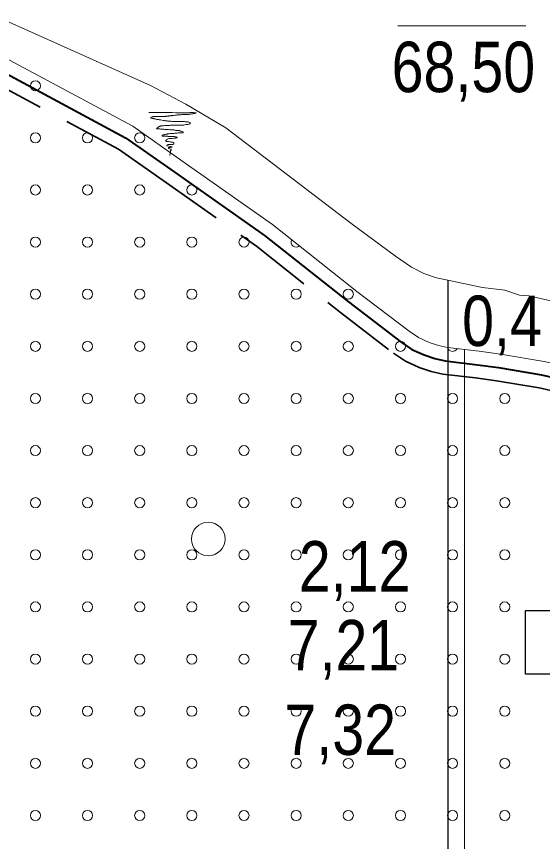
# Model space of a CAD drawing. Extents: x 640104 to 640970, y 6442278 to 6442689.
# Drawn here: x 640245.12 to 640276.39, y 6442589.62 to 6442638.69 of the extents above; entities that cross this region are included whole.
import ezdxf
from ezdxf.enums import TextEntityAlignment as Align

# ---------------------------------------------------------------- set-up
doc = ezdxf.new("R2010")
doc.units = 0
doc.header["$LTSCALE"] = 1.2
doc.linetypes.add('MEDIUM_DASHED', pattern=[4.5, 3, -1.5])
for name, color, linetype, lineweight in [('31', 7, 'Continuous', 13), ('32', 7, 'Continuous', 25), ('33', 7, 'Continuous', 13), ('35', 7, 'Continuous', 35), ('40', 7, 'Continuous', 13), ('43', 7, 'Continuous', 13), ('47', 7, 'Continuous', 13)]:
    doc.layers.add(name, color=color, linetype=linetype, lineweight=lineweight)

msp = doc.modelspace()

# ---------------------------------------------------------------- linework, layer by layer
at = {"layer": '31'}
for points in [[(640243.91, 6442638.69), (640253.09, 6442634.58), (640255.2, 6442633.48), (640257.56, 6442632.06), (640261.58, 6442629.01), (640265, 6442626.4), (640267.65, 6442624.44), (640268.61, 6442623.79), (640269.33, 6442623.41), (640270.09, 6442623.14), (640270.76, 6442623), (640271.59, 6442622.83), (640272.83, 6442622.58), (640274.15, 6442622.41), (640275.03, 6442622.12), (640275.59, 6442622.07), (640277.84, 6442621.56), (640282.07, 6442620.29), (640283.81, 6442619.85), (640292.79, 6442617.95), (640300.96, 6442616.04)], [(640244.14, 6442636.4), (640252.04, 6442632.16), (640254.96, 6442630.1), (640260.34, 6442626.31), (640265.36, 6442622.34), (640268.47, 6442619.97), (640269.03, 6442619.59), (640269.65, 6442619.31), (640270.21, 6442619.12), (640270.74, 6442619), (640272.62, 6442618.78), (640273.9, 6442618.6), (640276.5, 6442618.17), (640279.42, 6442617.51), (640285.18, 6442616.2), (640293.34, 6442614.31), (640302.22, 6442612.41), (640310.19, 6442611.24), (640319.16, 6442609.71), (640327.89, 6442607.76), (640337.5, 6442606.29), (640350.61, 6442605.07), (640361.71, 6442604.69)]]:
    msp.add_lwpolyline(points, dxfattribs=at)
at = {"layer": '32', "lineweight": 13}
msp.add_line((640267.79, 6442638.14), (640275.4, 6442638.14), dxfattribs=at)
at = {"layer": '32'}
msp.add_line((640270.76, 6442623), (640270.76, 6442501), dxfattribs=at)
at = {"layer": '33'}
msp.add_lwpolyline([(640271.76, 6442583), (640271.76, 6442618.88), (640270.76, 6442619), (640270.76, 6442583)], close=True, dxfattribs=at)
at = {"layer": '33', "lineweight": 25}
msp.add_lwpolyline([(640275.38, 6442603.37), (640284.09, 6442603.37), (640284.09, 6442599.57), (640275.38, 6442599.57)], close=True, dxfattribs=at)
at = {"layer": '35', "lineweight": 40}
msp.add_lwpolyline([(640243.75, 6442635.7), (640251.61, 6442631.47), (640254.5, 6442629.45), (640259.86, 6442625.67), (640264.87, 6442621.71), (640268, 6442619.32), (640268.63, 6442618.89), (640269.35, 6442618.56), (640270, 6442618.35), (640270.6, 6442618.21), (640272.52, 6442617.98), (640273.78, 6442617.81), (640276.34, 6442617.38), (640279.24, 6442616.73), (640285.01, 6442615.42), (640293.17, 6442613.53), (640302.08, 6442611.63), (640310.07, 6442610.45), (640319, 6442608.92), (640327.74, 6442606.97), (640337.4, 6442605.49), (640350.56, 6442604.27), (640361.69, 6442603.89)], dxfattribs=at)
at = {"layer": '35', "linetype": 'MEDIUM_DASHED'}
msp.add_lwpolyline([(640243.37, 6442635), (640251.19, 6442630.79), (640254.04, 6442628.79), (640259.39, 6442625.03), (640264.38, 6442621.08), (640267.53, 6442618.67), (640268.24, 6442618.19), (640269.06, 6442617.81), (640269.78, 6442617.57), (640270.47, 6442617.42), (640272.42, 6442617.19), (640273.66, 6442617.02), (640276.19, 6442616.6), (640279.06, 6442615.94), (640284.83, 6442614.64), (640292.99, 6442612.74), (640301.93, 6442610.84), (640309.94, 6442609.66), (640318.85, 6442608.14), (640327.59, 6442606.19), (640337.3, 6442604.7), (640350.51, 6442603.47), (640361.68, 6442603.09)], dxfattribs=at)
at = {"layer": '40'}
for points in [[(640252.99, 6442632.98), (640253.03, 6442632.98), (640253.1, 6442632.98), (640253.17, 6442632.98), (640253.19, 6442632.98), (640253.26, 6442632.98), (640253.36, 6442632.98), (640253.58, 6442632.98), (640253.7, 6442632.98), (640253.72, 6442632.98), (640253.75, 6442632.98), (640253.8, 6442632.98), (640253.85, 6442632.98), (640253.92, 6442632.98), (640253.98, 6442632.98), (640254.02, 6442632.98), (640254.08, 6442632.98), (640254.12, 6442632.98), (640254.17, 6442632.98), (640254.23, 6442632.98), (640254.26, 6442632.98), (640254.31, 6442632.98), (640254.37, 6442632.98), (640254.6, 6442632.97), (640254.8, 6442632.96), (640254.87, 6442632.96), (640254.91, 6442632.96), (640254.93, 6442632.96), (640254.96, 6442632.96), (640255.01, 6442632.96), (640255.08, 6442632.97), (640255.11, 6442632.97), (640255.13, 6442632.97), (640255.15, 6442632.97), (640255.17, 6442632.97), (640255.22, 6442632.96), (640255.24, 6442632.96), (640255.28, 6442632.96), (640255.34, 6442632.97), (640255.38, 6442632.97), (640255.43, 6442632.98), (640255.45, 6442632.98), (640255.5, 6442632.98), (640255.52, 6442632.99), (640255.56, 6442632.99), (640255.59, 6442632.99), (640255.61, 6442632.98), (640255.64, 6442632.98), (640255.67, 6442632.97), (640255.69, 6442632.97)], [(640254.01, 6442632.76), (640253.99, 6442632.75), (640253.95, 6442632.75), (640253.92, 6442632.74), (640253.9, 6442632.74), (640253.88, 6442632.74), (640253.84, 6442632.74), (640253.81, 6442632.74), (640253.78, 6442632.74), (640253.73, 6442632.74), (640253.71, 6442632.74), (640253.67, 6442632.75), (640253.64, 6442632.75), (640253.62, 6442632.75), (640253.6, 6442632.75), (640253.56, 6442632.75), (640253.53, 6442632.75), (640253.48, 6442632.75), (640253.46, 6442632.75), (640253.44, 6442632.75), (640253.4, 6442632.75), (640253.37, 6442632.75), (640253.34, 6442632.75), (640253.32, 6442632.75), (640253.28, 6442632.75), (640253.25, 6442632.74), (640253.23, 6442632.73), (640253.2, 6442632.73), (640253.17, 6442632.72), (640253.16, 6442632.71), (640253.14, 6442632.7), (640253.12, 6442632.69), (640253.12, 6442632.66), (640253.12, 6442632.64), (640253.19, 6442632.63), (640253.23, 6442632.63), (640253.25, 6442632.62), (640253.28, 6442632.62), (640253.31, 6442632.61), (640253.32, 6442632.6), (640253.36, 6442632.6), (640253.4, 6442632.59), (640253.42, 6442632.58), (640253.47, 6442632.57), (640253.52, 6442632.56), (640253.56, 6442632.56), (640253.6, 6442632.55), (640253.63, 6442632.54), (640253.68, 6442632.54), (640253.76, 6442632.53)], [(640253.76, 6442632.53), (640253.85, 6442632.51), (640253.92, 6442632.5), (640253.96, 6442632.49), (640254.02, 6442632.48), (640254.08, 6442632.48), (640254.13, 6442632.47), (640254.17, 6442632.47), (640254.2, 6442632.46), (640254.26, 6442632.46), (640254.3, 6442632.46), (640254.36, 6442632.45), (640254.41, 6442632.45), (640254.46, 6442632.45), (640254.52, 6442632.45), (640254.58, 6442632.44), (640254.62, 6442632.44), (640254.64, 6442632.44), (640254.69, 6442632.44), (640254.74, 6442632.44), (640254.8, 6442632.44), (640254.86, 6442632.44), (640254.92, 6442632.44), (640254.96, 6442632.44), (640255.01, 6442632.44), (640255.04, 6442632.44), (640255.08, 6442632.44), (640255.12, 6442632.44), (640255.16, 6442632.43), (640255.2, 6442632.43), (640255.23, 6442632.42), (640255.32, 6442632.42), (640255.36, 6442632.4), (640255.4, 6442632.38), (640255.43, 6442632.38), (640255.45, 6442632.37), (640255.45, 6442632.34), (640255.44, 6442632.32), (640255.43, 6442632.31), (640255.41, 6442632.3), (640255.4, 6442632.29), (640255.36, 6442632.28), (640255.31, 6442632.26), (640255.21, 6442632.26), (640255.12, 6442632.24), (640255.08, 6442632.23), (640255.01, 6442632.23), (640254.96, 6442632.22), (640254.89, 6442632.22), (640254.8, 6442632.22), (640254.68, 6442632.22), (640254.56, 6442632.22)], [(640255.69, 6442632.97), (640255.72, 6442632.96), (640255.75, 6442632.96), (640255.78, 6442632.96), (640255.8, 6442632.94), (640255.78, 6442632.94), (640255.79, 6442632.94), (640255.76, 6442632.94), (640255.73, 6442632.93), (640255.69, 6442632.92), (640255.67, 6442632.92), (640255.64, 6442632.92), (640255.61, 6442632.91), (640255.59, 6442632.91), (640255.57, 6442632.9), (640255.53, 6442632.9), (640255.48, 6442632.89), (640255.46, 6442632.89), (640255.38, 6442632.88), (640255.35, 6442632.87), (640255.32, 6442632.87), (640255.29, 6442632.86), (640255.26, 6442632.86), (640255.24, 6442632.86), (640255.2, 6442632.86), (640255.17, 6442632.86), (640255.1, 6442632.86), (640255.06, 6442632.86), (640255.01, 6442632.86), (640254.96, 6442632.86), (640254.92, 6442632.85), (640254.88, 6442632.85), (640254.84, 6442632.84), (640254.8, 6442632.84), (640254.69, 6442632.84), (640254.67, 6442632.84), (640254.64, 6442632.83), (640254.6, 6442632.82), (640254.53, 6442632.82), (640254.48, 6442632.81), (640254.44, 6442632.81), (640254.38, 6442632.8), (640254.34, 6442632.8), (640254.31, 6442632.78), (640254.27, 6442632.78), (640254.25, 6442632.78), (640254.23, 6442632.78), (640254.19, 6442632.78), (640254.16, 6442632.77), (640254.13, 6442632.77), (640254.04, 6442632.76), (640254.01, 6442632.76)], [(640254.56, 6442632.22), (640254.51, 6442632.22), (640254.46, 6442632.22), (640254.4, 6442632.22), (640254.36, 6442632.22), (640254.32, 6442632.22), (640254.27, 6442632.22), (640254.21, 6442632.21), (640254.09, 6442632.21), (640254.04, 6442632.21), (640254, 6442632.2), (640253.95, 6442632.2), (640253.87, 6442632.18), (640253.78, 6442632.18), (640253.75, 6442632.18), (640253.71, 6442632.18), (640253.69, 6442632.17), (640253.67, 6442632.16), (640253.64, 6442632.16), (640253.62, 6442632.15), (640253.6, 6442632.14), (640253.58, 6442632.13), (640253.54, 6442632.1), (640253.52, 6442632.09), (640253.51, 6442632.07), (640253.48, 6442632.06), (640253.48, 6442632.05), (640253.46, 6442632.03), (640253.45, 6442632.02), (640253.47, 6442632.01), (640253.49, 6442632.01), (640253.53, 6442632.01), (640253.56, 6442632.01), (640253.64, 6442632), (640253.69, 6442631.99), (640253.76, 6442631.98), (640253.84, 6442631.98), (640253.88, 6442631.98), (640253.92, 6442631.96), (640253.96, 6442631.96), (640254.07, 6442631.96), (640254.16, 6442631.96), (640254.23, 6442631.95), (640254.3, 6442631.94), (640254.4, 6442631.94), (640254.49, 6442631.94), (640254.57, 6442631.91), (640254.63, 6442631.91), (640254.69, 6442631.91), (640254.75, 6442631.9)], [(640254.75, 6442631.9), (640254.78, 6442631.9), (640254.81, 6442631.9), (640254.87, 6442631.88), (640254.92, 6442631.87), (640254.95, 6442631.86), (640254.98, 6442631.85), (640255.02, 6442631.84), (640255.04, 6442631.83), (640255.04, 6442631.8), (640255.03, 6442631.79), (640255.01, 6442631.78), (640254.99, 6442631.78), (640254.91, 6442631.77), (640254.87, 6442631.77), (640254.84, 6442631.77), (640254.8, 6442631.77), (640254.74, 6442631.77), (640254.68, 6442631.76), (640254.65, 6442631.76), (640254.62, 6442631.76), (640254.53, 6442631.76), (640254.48, 6442631.74), (640254.46, 6442631.74), (640254.42, 6442631.74), (640254.4, 6442631.74), (640254.36, 6442631.74), (640254.3, 6442631.74), (640254.25, 6442631.73), (640254.2, 6442631.72), (640254.16, 6442631.71), (640254.13, 6442631.71), (640254.1, 6442631.71), (640254.08, 6442631.7), (640254.04, 6442631.7), (640254.03, 6442631.69), (640253.99, 6442631.68), (640253.97, 6442631.67), (640253.95, 6442631.67), (640253.92, 6442631.66), (640253.88, 6442631.66), (640253.84, 6442631.65), (640253.8, 6442631.63), (640253.79, 6442631.62), (640253.79, 6442631.58), (640253.81, 6442631.58), (640253.86, 6442631.58), (640253.92, 6442631.58), (640253.98, 6442631.58), (640254.01, 6442631.58), (640254.08, 6442631.57), (640254.12, 6442631.57)], [(640254.12, 6442631.57), (640254.13, 6442631.56), (640254.16, 6442631.56), (640254.2, 6442631.56), (640254.24, 6442631.56), (640254.27, 6442631.56), (640254.34, 6442631.55), (640254.4, 6442631.55), (640254.42, 6442631.55), (640254.45, 6442631.55), (640254.48, 6442631.55), (640254.52, 6442631.55), (640254.56, 6442631.54), (640254.59, 6442631.53), (640254.62, 6442631.52), (640254.65, 6442631.51), (640254.68, 6442631.5), (640254.68, 6442631.47), (640254.6, 6442631.46), (640254.49, 6442631.45), (640254.45, 6442631.45), (640254.38, 6442631.44), (640254.34, 6442631.44), (640254.29, 6442631.44), (640254.24, 6442631.43), (640254.2, 6442631.43), (640254.15, 6442631.42), (640254.09, 6442631.39), (640254.08, 6442631.38), (640254.04, 6442631.36), (640254.03, 6442631.34), (640254.01, 6442631.33), (640254, 6442631.3), (640253.99, 6442631.28), (640254, 6442631.27), (640254.04, 6442631.26), (640254.08, 6442631.25), (640254.17, 6442631.25), (640254.24, 6442631.24), (640254.28, 6442631.23), (640254.32, 6442631.22), (640254.36, 6442631.22), (640254.42, 6442631.22), (640254.48, 6442631.19), (640254.48, 6442631.16), (640254.48, 6442631.14), (640254.47, 6442631.12), (640254.42, 6442631.08), (640254.4, 6442631.07), (640254.36, 6442631.07), (640254.3, 6442631.07), (640254.24, 6442631.07), (640254.2, 6442631.07), (640254.14, 6442631.07), (640254.08, 6442631.06), (640254.08, 6442631.03), (640254.07, 6442631.02), (640254.08, 6442631), (640254.1, 6442630.99), (640254.18, 6442630.97), (640254.24, 6442630.96), (640254.27, 6442630.95), (640254.31, 6442630.94), (640254.35, 6442630.94), (640254.37, 6442630.92), (640254.36, 6442630.91), (640254.32, 6442630.91), (640254.27, 6442630.9), (640254.2, 6442630.9), (640254.18, 6442630.9), (640254.16, 6442630.89), (640254.16, 6442630.86), (640254.17, 6442630.84), (640254.19, 6442630.83), (640254.21, 6442630.82), (640254.24, 6442630.81), (640254.28, 6442630.8), (640254.32, 6442630.79), (640254.32, 6442630.76), (640254.31, 6442630.74), (640254.3, 6442630.72), (640254.28, 6442630.7), (640254.27, 6442630.68), (640254.27, 6442630.65), (640254.27, 6442630.62), (640254.27, 6442630.59), (640254.26, 6442630.57), (640254.26, 6442630.54), (640254.25, 6442630.52), (640254.24, 6442630.49), (640254.24, 6442630.46), (640254.24, 6442630.43), (640254.24, 6442630.42), (640254.24, 6442630.45)]]:
    msp.add_lwpolyline(points, dxfattribs=at)
at = {"layer": '43'}
for centre in [(640246.249, 6442634.573), (640246.249, 6442631.473), (640249.349, 6442631.473), (640252.449, 6442631.473), (640246.249, 6442628.373), (640249.349, 6442628.373), (640252.449, 6442628.373), (640255.549, 6442628.373), (640246.249, 6442625.273), (640249.349, 6442625.273), (640252.449, 6442625.273), (640255.549, 6442625.273), (640258.649, 6442625.273), (640246.249, 6442622.173), (640249.349, 6442622.173), (640252.449, 6442622.173), (640255.549, 6442622.173), (640258.649, 6442622.173), (640261.749, 6442622.173), (640264.849, 6442622.173), (640246.249, 6442619.073), (640249.349, 6442619.073), (640252.449, 6442619.073), (640255.549, 6442619.073), (640258.649, 6442619.073), (640261.749, 6442619.073), (640264.849, 6442619.073), (640267.949, 6442619.073), (640246.249, 6442615.973), (640249.349, 6442615.973), (640252.449, 6442615.973), (640255.549, 6442615.973), (640258.649, 6442615.973), (640261.749, 6442615.973), (640264.849, 6442615.973), (640267.949, 6442615.973), (640271.049, 6442615.973), (640274.149, 6442615.973), (640246.249, 6442612.873), (640249.349, 6442612.873), (640252.449, 6442612.873), (640255.549, 6442612.873), (640258.649, 6442612.873), (640261.749, 6442612.873), (640264.849, 6442612.873), (640267.949, 6442612.873), (640271.049, 6442612.873), (640274.149, 6442612.873), (640246.249, 6442609.773), (640249.349, 6442609.773), (640252.449, 6442609.773), (640255.549, 6442609.773), (640258.649, 6442609.773), (640261.749, 6442609.773), (640264.849, 6442609.773), (640267.949, 6442609.773), (640271.049, 6442609.773), (640274.149, 6442609.773), (640246.249, 6442606.673), (640249.349, 6442606.673), (640252.449, 6442606.673), (640255.549, 6442606.673), (640258.649, 6442606.673), (640261.749, 6442606.673), (640264.849, 6442606.673), (640267.949, 6442606.673), (640271.049, 6442606.673), (640274.149, 6442606.673), (640246.249, 6442603.573), (640249.349, 6442603.573), (640252.449, 6442603.573), (640255.549, 6442603.573), (640258.649, 6442603.573), (640261.749, 6442603.573), (640264.849, 6442603.573), (640267.949, 6442603.573), (640271.049, 6442603.573), (640274.149, 6442603.573), (640246.249, 6442600.473), (640249.349, 6442600.473), (640252.449, 6442600.473), (640255.549, 6442600.473), (640258.649, 6442600.473), (640261.749, 6442600.473), (640264.849, 6442600.473), (640267.949, 6442600.473), (640271.049, 6442600.473), (640274.149, 6442600.473), (640246.249, 6442597.373), (640249.349, 6442597.373), (640252.449, 6442597.373), (640255.549, 6442597.373), (640258.649, 6442597.373), (640261.749, 6442597.373), (640264.849, 6442597.373), (640267.949, 6442597.373), (640271.049, 6442597.373), (640274.149, 6442597.373), (640246.249, 6442594.273), (640249.349, 6442594.273), (640252.449, 6442594.273), (640255.549, 6442594.273), (640258.649, 6442594.273), (640261.749, 6442594.273), (640264.849, 6442594.273), (640267.949, 6442594.273), (640271.049, 6442594.273), (640274.149, 6442594.273), (640246.249, 6442591.173), (640249.349, 6442591.173), (640252.449, 6442591.173), (640255.549, 6442591.173), (640258.649, 6442591.173), (640261.749, 6442591.173), (640264.849, 6442591.173), (640267.949, 6442591.173), (640271.049, 6442591.173), (640274.149, 6442591.173)]:
    msp.add_circle(centre, 0.3, dxfattribs=at)
for centre, start, end in [((640261.749, 6442625.273), 152.434, 310.8845), ((640271.049, 6442619.073), 194.3988, 332.1403)]:
    msp.add_arc(centre, 0.3, start, end, dxfattribs=at)
at = {"layer": '47'}
msp.add_circle((640256.523, 6442607.614), 1, dxfattribs=at)

# ---------------------------------------------------------------- texts
at = {"layer": '32', "width": 0.85}
for s, p in [('68,50', (640271.69, 6442634.19)), ('0,4', (640273.985, 6442619.09))]:
    msp.add_text(s, height=3, dxfattribs=at).set_placement(p, align=Align.CENTER)
at = {"layer": '33', "width": 0.85}
for s, p in [('2,12', (640265.225, 6442604.49)), ('7,21', (640264.56, 6442599.8)), ('7,32', (640264.37, 6442594.77))]:
    msp.add_text(s, height=3, dxfattribs=at).set_placement(p, align=Align.CENTER)

doc.saveas('drawing.dxf')
